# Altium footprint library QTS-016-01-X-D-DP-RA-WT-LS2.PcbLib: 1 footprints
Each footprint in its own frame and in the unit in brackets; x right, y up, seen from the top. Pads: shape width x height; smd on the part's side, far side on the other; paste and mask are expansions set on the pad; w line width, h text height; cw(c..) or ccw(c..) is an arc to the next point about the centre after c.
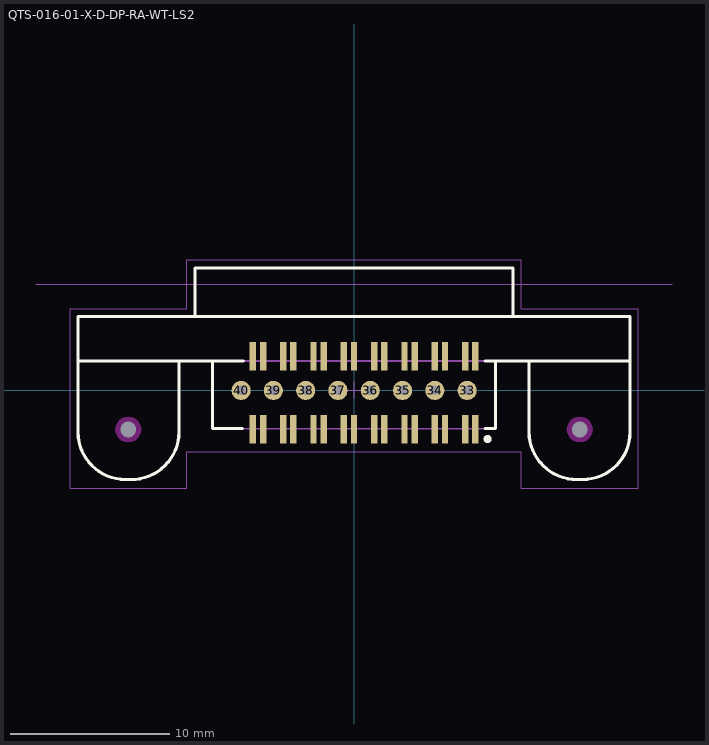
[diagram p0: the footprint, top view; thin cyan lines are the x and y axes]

## QTS-016-01-X-D-DP-RA-WT-LS2 [mm] "0.635mm pitch, 16 pin, terminal strip; r/a, double row"
height 9.42
pads (42):
  rect 0.4x1.8 smd mask+0: 1(7.622,-2.45) 2(7.622,2.16) 3(6.981,-2.45) 4(6.981,2.16) 5(5.717,-2.45) 6(5.717,2.16) 7(5.076,-2.45) 8(5.076,2.16) 9(3.812,-2.45) 10(3.812,2.16) 11(3.171,-2.45) 12(3.171,2.16) 13(1.907,-2.45) 14(1.907,2.16) 15(1.266,-2.45) 16(1.266,2.16) 17(0.002,-2.45) 18(0.002,2.16) 19(-0.639,-2.45) 20(-0.639,2.16) 21(-1.903,-2.45) 22(-1.903,2.16) 23(-2.544,-2.45) 24(-2.544,2.16) 25(-3.808,-2.45) 26(-3.808,2.16) 27(-4.449,-2.45) 28(-4.449,2.16) 29(-5.713,-2.45) 30(-5.713,2.16) 31(-6.354,-2.45) 32(-6.354,2.16)
  round 1.2 hole 0.6 mask+0: 33(7.111,0) 34(5.082,0) 35(3.052,0) 36(1.021,0) 37(-1.008,0) 38(-3.039,0) 39(-5.068,0) 40(-7.098,0)
  round 0.5 hole 1 unplated mask+0: 41(14.192,-2.45) 42(-14.192,-2.45)
Top Overlay:
  circle w0.25: c8.4,-3.05 r0.125
  lines w0.2: -17.35,1.86 -17.35,-2.625 ccw(c-14.349,-2.599) -14.365,-5.6 ; -14.366,-5.6 -14.016,-5.6 ccw(c-13.996,-2.604) -11,-2.625 -11,1.85 ; -10,4.66 -10,7.7 10,7.7 10,4.66 ; -8.9,1.85 -8.9,-2.4 -7,-2.4 ; -6.95,1.85 -17.35,1.85 -17.35,4.65 17.35,4.65 17.35,1.85 8.25,1.85 ; 8.25,-2.4 8.9,-2.4 8.9,1.85 ; 11,1.85 11,-2.625 ccw(c14.001,-2.599) 14.017,-5.6 14.366,-5.6 ccw(c14.366,-2.616) 17.35,-2.627 ; 17.35,-2.625 17.35,1.86
Keep-Out Layer:
  pour cut-out: -13.385,-2.45 -13.413,-2.241 -13.493,-2.047 -13.621,-1.879 -13.789,-1.751 -13.983,-1.671 -14.192,-1.643 -14.401,-1.671 -14.595,-1.751 -14.763,-1.879 -14.891,-2.047 -14.971,-2.241 -14.999,-2.45 -14.971,-2.659 -14.891,-2.853 -14.763,-3.021 -14.595,-3.149 -14.401,-3.229 -14.192,-3.257 -13.983,-3.229 -13.789,-3.149 -13.621,-3.021 -13.493,-2.853 -13.413,-2.659
  pour cut-out: 14.999,-2.45 14.971,-2.241 14.891,-2.047 14.763,-1.879 14.595,-1.751 14.401,-1.671 14.192,-1.643 13.983,-1.671 13.789,-1.751 13.621,-1.879 13.493,-2.047 13.413,-2.241 13.385,-2.45 13.413,-2.659 13.493,-2.853 13.621,-3.021 13.789,-3.149 13.983,-3.229 14.192,-3.257 14.401,-3.229 14.595,-3.149 14.763,-3.021 14.891,-2.853 14.971,-2.659
Mechanical 12:
  lines w0.001: -20,6.69 20,6.69 ; -17.35,-2.6 -17.35,4.65 -10,4.65 -10,7.7 10,7.7 10,4.65 17.35,4.65 17.35,-2.6 ; -14.35,-5.6 -14,-5.6 ; -11,-2.6 -11,1.85 -8.9,1.85 -8.9,-2.4 8.9,-2.4 8.9,1.85 11,1.85 11,-2.6 ; 14,-5.6 14.35,-5.6
Mechanical 13:
  lines w0.1: -17.35,-2.626 ccw(c-14.371,-2.621) -14.366,-5.6 ; -17.35,-2.625 -17.35,1.86 ; -14.366,-5.6 -14.016,-5.6 ccw(c-14.001,-2.599) -11,-2.625 -11,1.85 ; -10,4.66 -10,7.7 10,7.7 10,4.66 ; -8.9,1.85 -8.9,-2.4 8.9,-2.4 8.9,1.85 ; 11,1.85 11,-2.625 ccw(c13.996,-2.604) 14.017,-5.6 14.366,-5.6 ; 14.365,-5.6 ccw(c14.349,-2.599) 17.35,-2.625 17.35,1.86 ; -17.35,1.85 -17.35,4.65 17.35,4.65 17.35,1.85 -17.35,1.85
  text ".Designator" at 0,-0.127 h1.52
Mechanical 15:
  lines w0.05: -0.5,0 0.5,0 ; 0,-0.5 0,0.5 ; -17.85,-6.15 -17.85,5.15 -10.5,5.15 -10.5,8.218 10.5,8.218 10.5,5.15 17.875,5.15 17.875,-6.133 10.509,-6.133 10.509,-3.85 -10.509,-3.85 -10.509,-6.15 -17.85,-6.15
Mechanical 16:
  lines w0.001: -17.35,-2.6 ccw(c-14.35,-2.6) -14.35,-5.6 ; -14,-5.6 ccw(c-14,-2.6) -11,-2.6 ; 11,-2.6 ccw(c14,-2.6) 14,-5.6 ; 14.35,-5.6 ccw(c14.35,-2.6) 17.35,-2.6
